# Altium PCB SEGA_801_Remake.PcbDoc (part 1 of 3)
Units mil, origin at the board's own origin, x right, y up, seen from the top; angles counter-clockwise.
Board outline 5905.51 x 7590.41 mil, 2 copper layers (Top Layer, Bottom Layer), stack 61.811 mil thick; 192 components, 203 nets, 858 pads, 614 vias.
Unrouted connection lines stored in the file: 107.
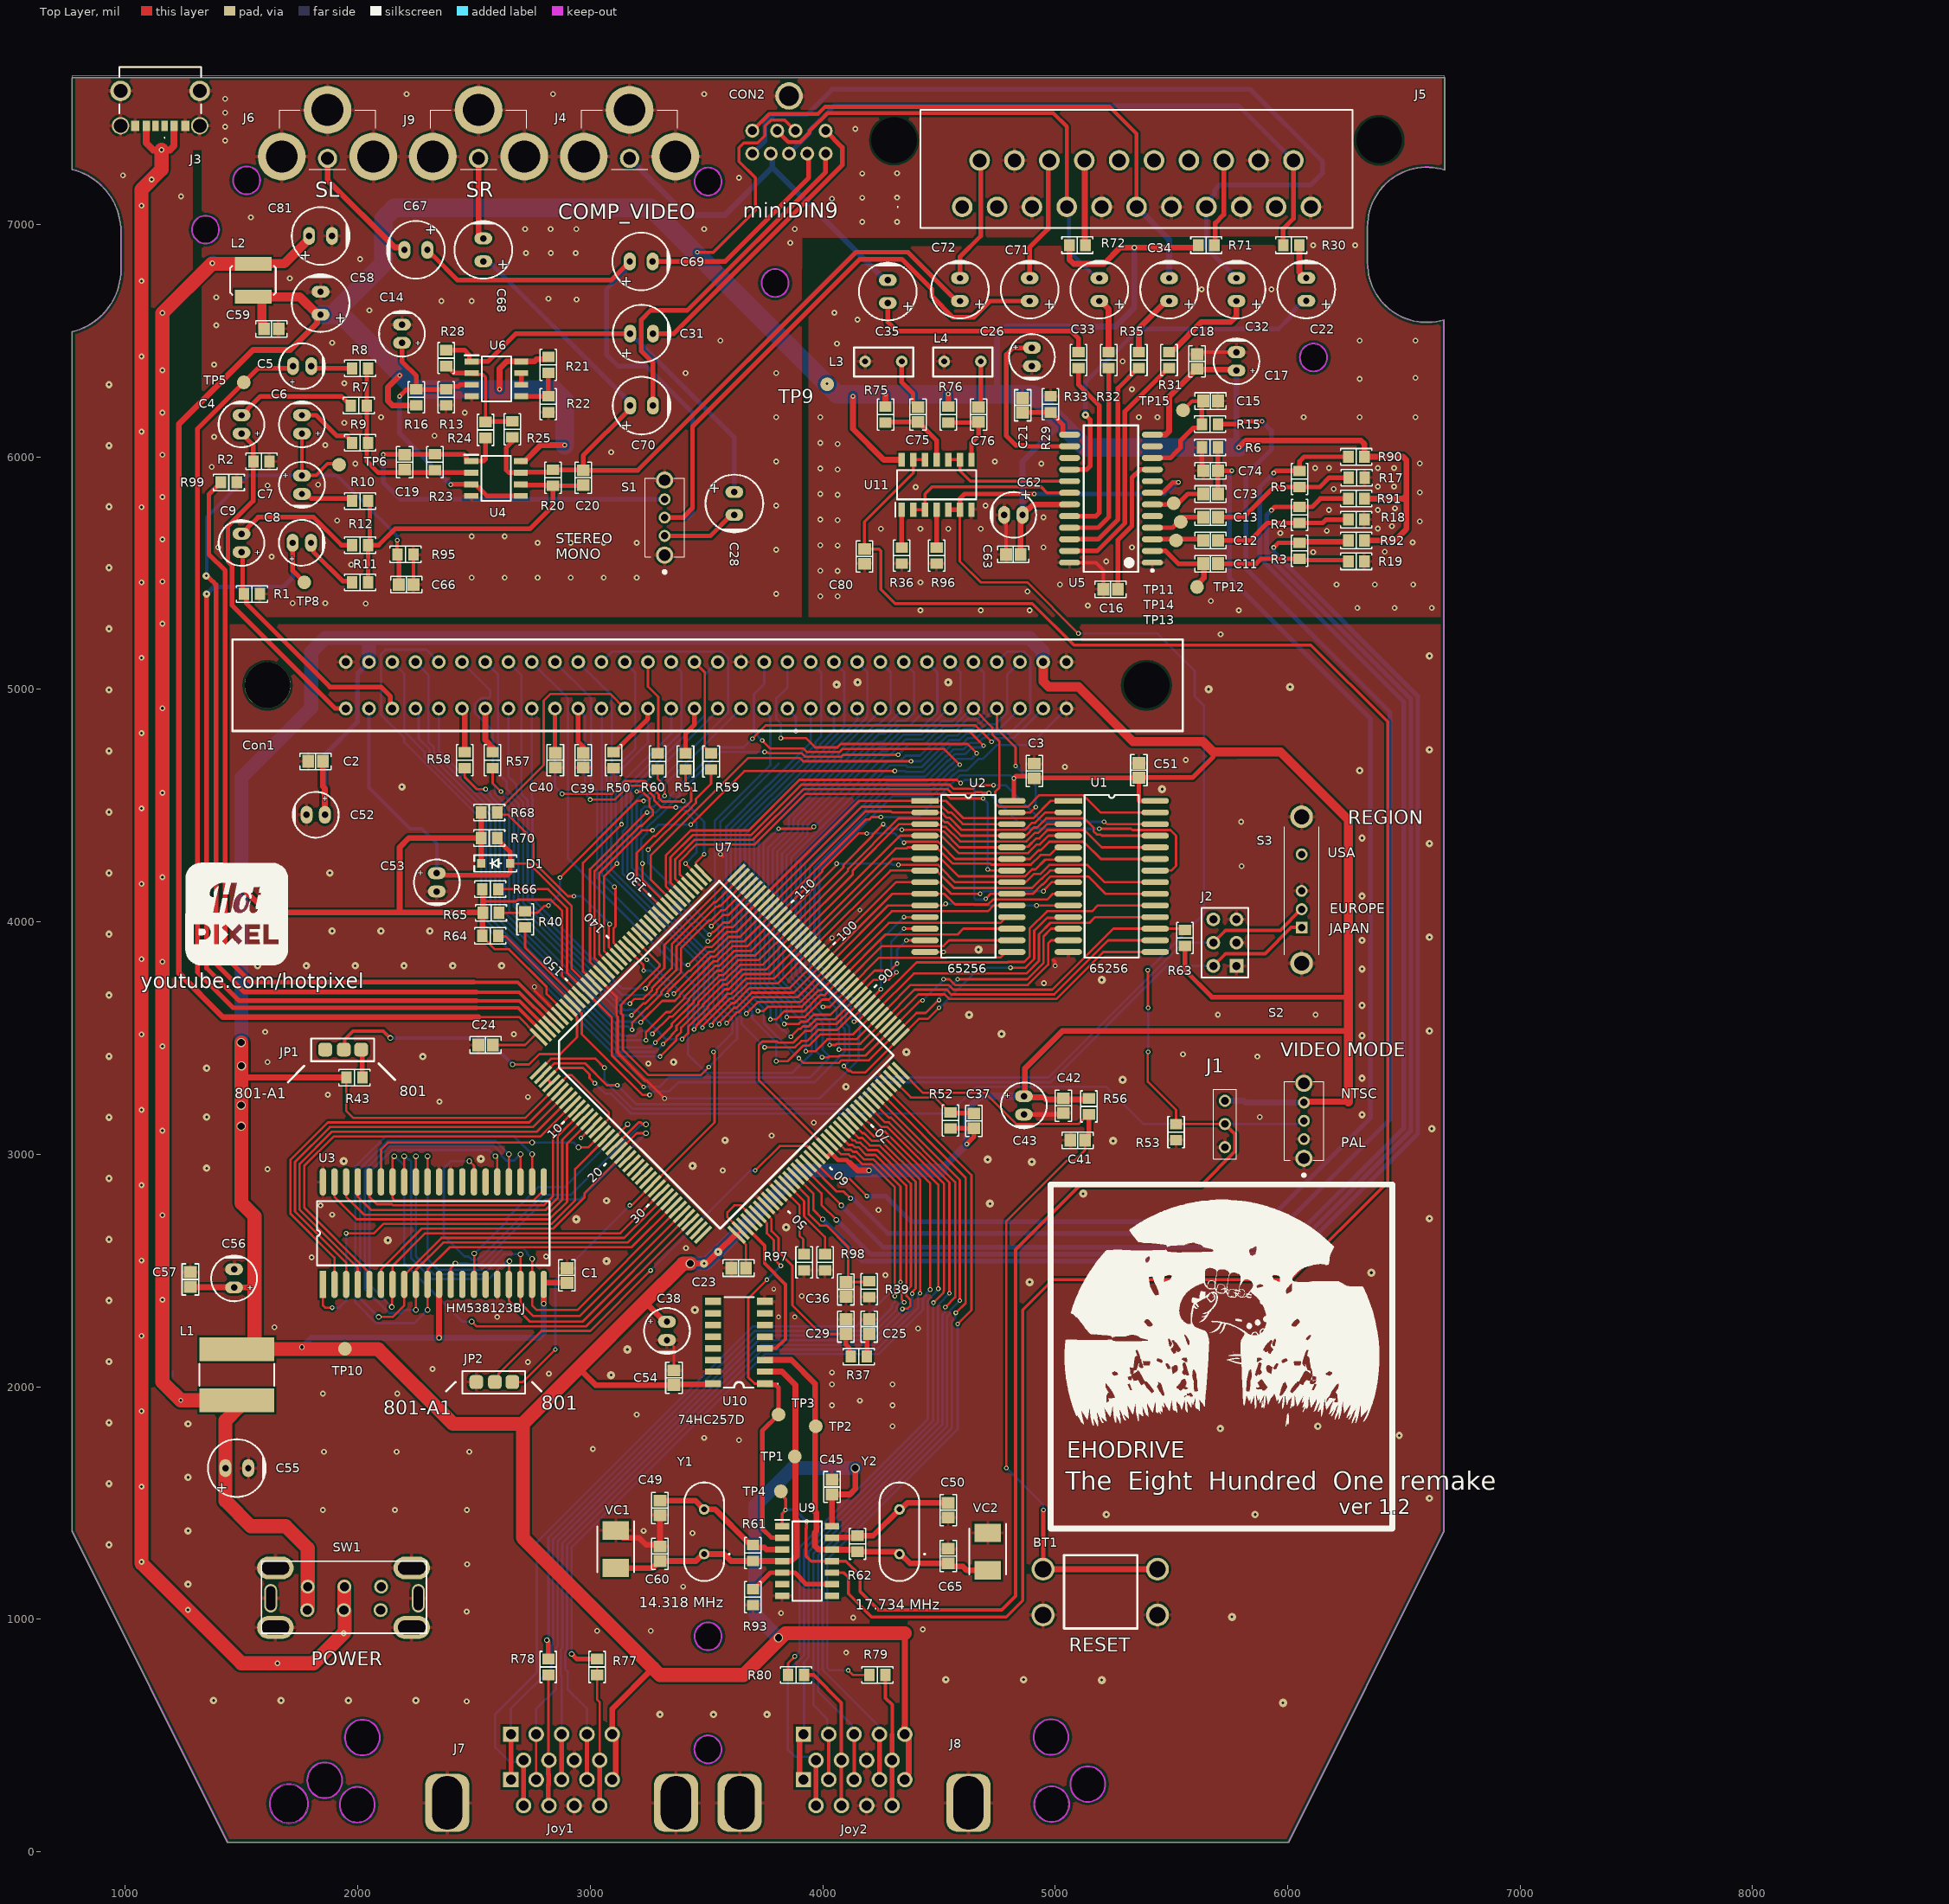
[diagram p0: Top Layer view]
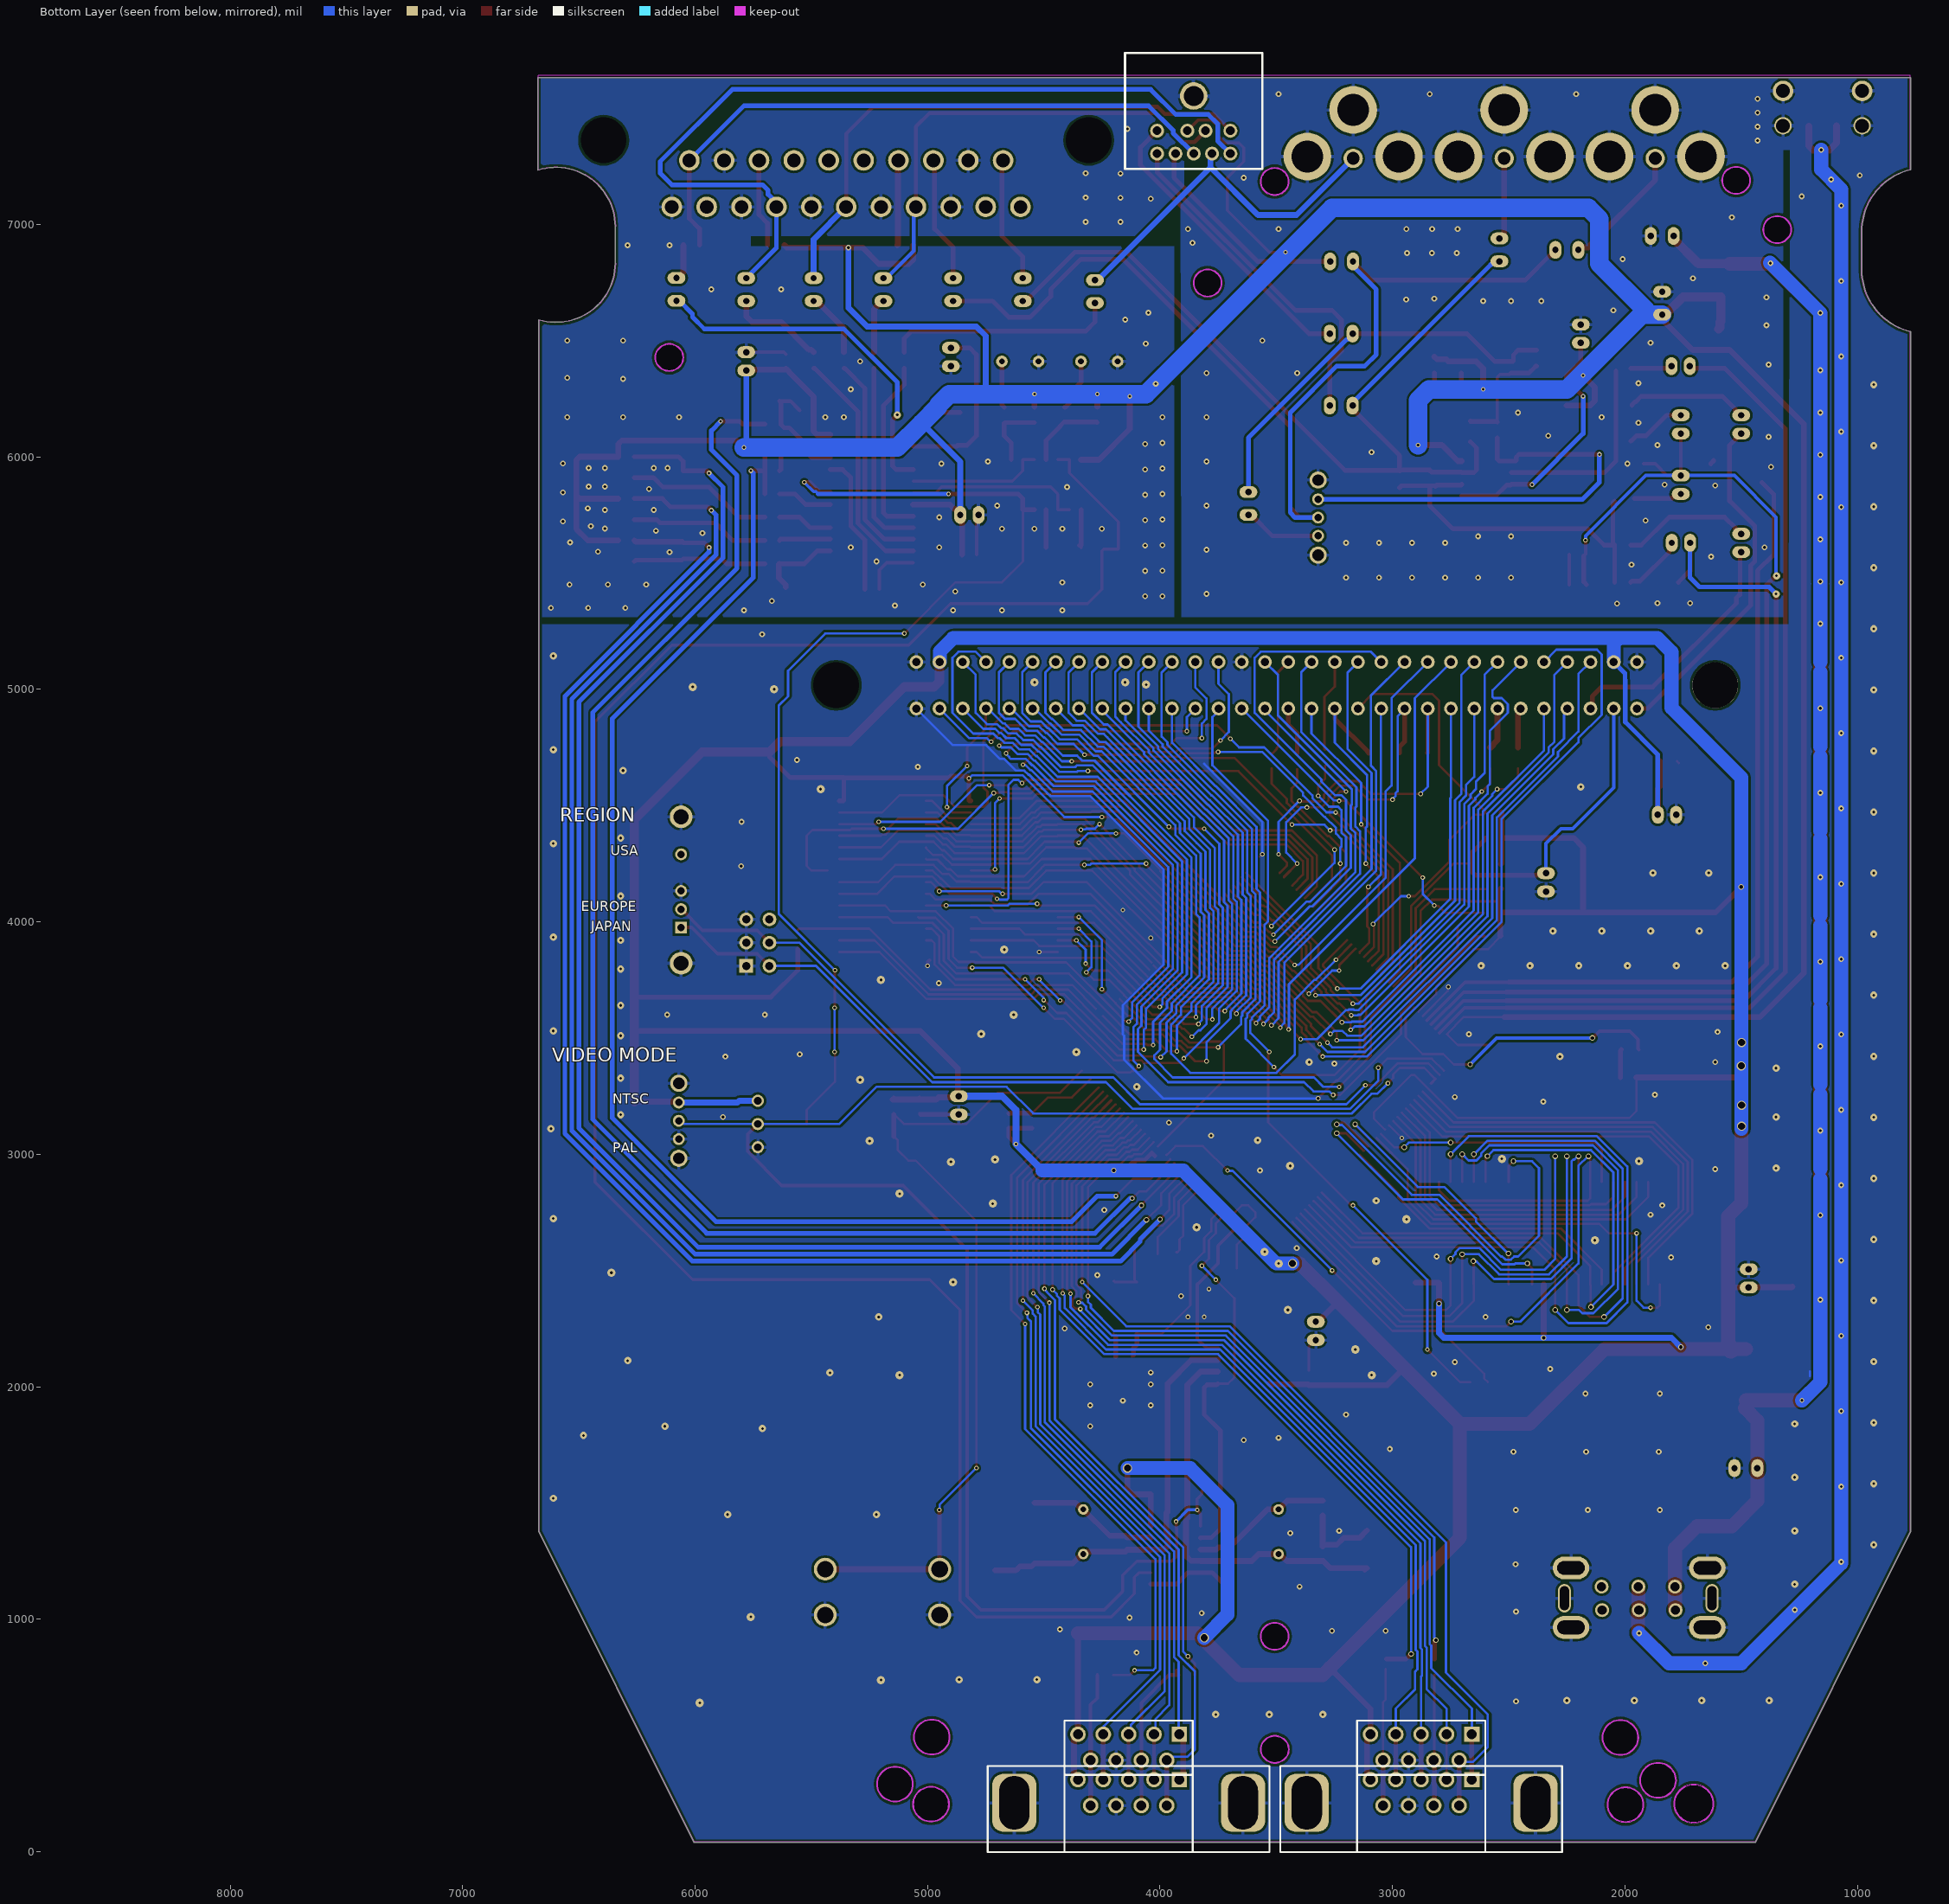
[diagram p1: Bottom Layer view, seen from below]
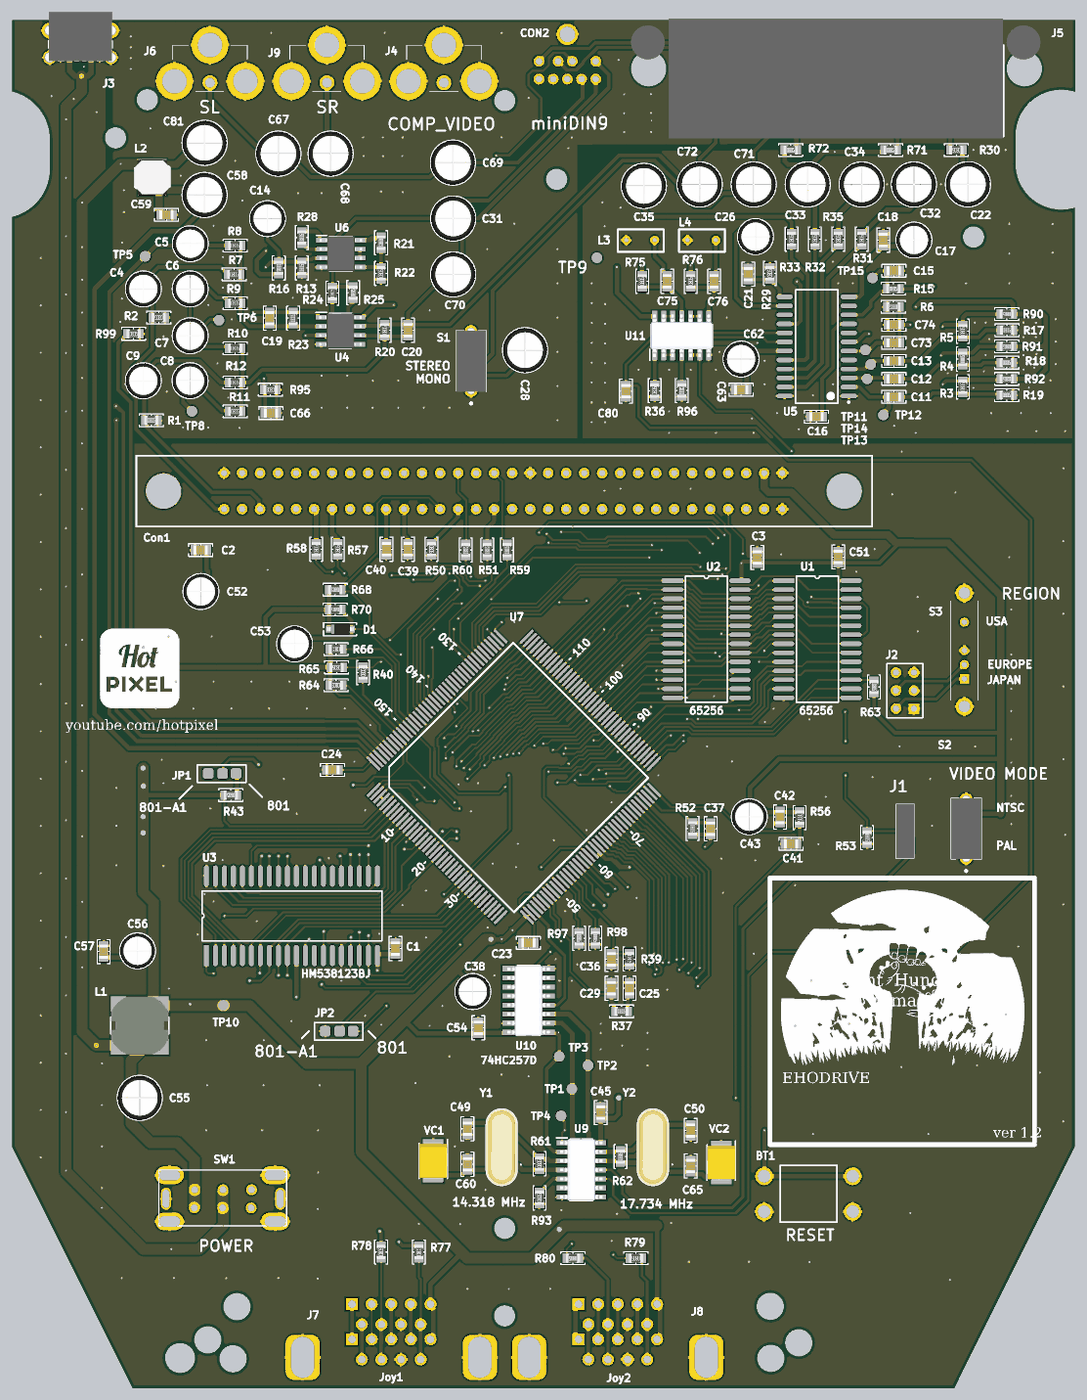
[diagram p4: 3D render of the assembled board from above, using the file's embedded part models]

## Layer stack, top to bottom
Top Solder: solder mask 0.9843, SM-004, Dk 4
Top Layer: signal copper 1.378
Dielectric 1: core 59.0551, FR4 Tg135, Dk 4.5
Bottom Layer: signal copper 1.378
Bottom Solder: solder mask 0.9843, SM-004, Dk 4

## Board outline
771,1378.35 771,6538.46 ccw(c705.6,6806.38) 981.38,6806.38 981.38,6967.36 ccw(c705.6,6967.36) 771,7235.27 771,7630 6676.51,7630 6676.51,7232.75 6676.15,7232.75 ccw(c6598.39,6990.56) 6344.02,6990.56 6344.02,6833.17 ccw(c6598.39,6833.17) 6672.57,6589.85 6672.57,1378.35 6004.03,39.59 1439.54,39.59
cut-out: 1922.01,201.93 ccw(c1997.86,201.93) 1997.86,126.08 ccw(c1997.86,201.93) 2073.71,201.93 ccw(c1997.86,201.93) 1997.86,277.78 ccw(c1997.86,201.93)
cut-out: 3736.39,6747.4 ccw(c3795.44,6747.4) 3795.44,6688.35 ccw(c3795.44,6747.4) 3854.5,6747.4 ccw(c3795.44,6747.4) 3795.44,6806.46 ccw(c3795.44,6747.4)
cut-out: 3448.14,7184.1 ccw(c3507.19,7184.1) 3507.19,7125.05 ccw(c3507.19,7184.1) 3566.25,7184.1 ccw(c3507.19,7184.1) 3507.19,7243.16 ccw(c3507.19,7184.1)
cut-out: 1463.14,7189.1 ccw(c1522.19,7189.1) 1522.19,7130.05 ccw(c1522.19,7189.1) 1581.25,7189.1 ccw(c1522.19,7189.1) 1522.19,7248.16 ccw(c1522.19,7189.1)
cut-out: 4909.15,204.15 ccw(c4985,204.15) 4985,128.3 ccw(c4985,204.15) 5060.85,204.15 ccw(c4985,204.15) 4985,280 ccw(c4985,204.15)
cut-out: 5064.35,290.61 ccw(c5140.2,290.61) 5140.2,214.75 ccw(c5140.2,290.61) 5216.05,290.61 ccw(c5140.2,290.61) 5140.2,366.46 ccw(c5140.2,290.61)
cut-out: 4906.08,492.86 ccw(c4981.93,492.86) 4981.93,417.01 ccw(c4981.93,492.86) 5057.78,492.86 ccw(c4981.93,492.86) 4981.93,568.71 ccw(c4981.93,492.86)
cut-out: 1944.07,490.97 ccw(c2019.92,490.97) 2019.92,415.12 ccw(c2019.92,490.97) 2095.77,490.97 ccw(c2019.92,490.97) 2019.92,566.82 ccw(c2019.92,490.97)
cut-out: 6051.84,6427.19 ccw(c6110.9,6427.19) 6110.9,6368.14 ccw(c6110.9,6427.19) 6169.95,6427.19 ccw(c6110.9,6427.19) 6110.9,6486.25 ccw(c6110.9,6427.19)
cut-out: 1286.39,6977.4 ccw(c1345.44,6977.4) 1345.44,6918.35 ccw(c1345.44,6977.4) 1404.5,6977.4 ccw(c1345.44,6977.4) 1345.44,7036.46 ccw(c1345.44,6977.4)
cut-out: 3448.04,925.94 ccw(c3507.09,925.94) 3507.09,866.89 ccw(c3507.09,925.94) 3566.15,925.94 ccw(c3507.09,925.94) 3507.09,985 ccw(c3507.09,925.94)
cut-out: 3447.16,439.94 ccw(c3506.22,439.94) 3506.22,380.88 ccw(c3506.22,439.94) 3565.27,439.94 ccw(c3506.22,439.94) 3506.22,498.99 ccw(c3506.22,439.94)
cut-out: 1782.01,306.93 ccw(c1857.86,306.93) 1857.86,231.08 ccw(c1857.86,306.93) 1933.71,306.93 ccw(c1857.86,306.93) 1857.86,382.78 ccw(c1857.86,306.93)
cut-out: 1620.59,206.07 cw(c1703.93,206.07) 1703.93,289.41 cw(c1703.93,206.07) 1787.27,206.07 cw(c1703.93,206.07) 1703.93,122.73 cw(c1703.93,206.07)

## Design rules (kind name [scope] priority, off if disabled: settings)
BoardOutlineClearance [All] p1 off: gap=10 ignorepadtopadclearanceinfootprint=FALSE except(0: Arc-SplitContinuation Track-SplitContinuation SMDPad-SplitContinuation THPad-SplitContinuation Via-SplitContinuation Fill-SplitContinuation Poly-SplitContinuation Region-SplitContinuation Text-SplitContinuation)
Clearance Clearance_Gen [InNetClass('GEN')] p1: gap=20 ignorepadtopadclearanceinfootprint=TRUE except(40: Track-Poly)
Clearance Clearance_ram [InNetClass('RAM bus')] p2: gap=10 ignorepadtopadclearanceinfootprint=TRUE except(5: Arc-SMDPad Track-SMDPad)
Clearance [All] p3 off: gap=10 ignorepadtopadclearanceinfootprint=FALSE except(0: Arc-Hole Track-Hole SMDPad-Hole THPad-Hole Via-Hole Fill-Hole Poly-Hole Region-Hole Text-Hole)
Clearance Clearance_analog [InNetClass('Analog')] p4: gap=20 ignorepadtopadclearanceinfootprint=TRUE
Clearance Clearance_dig [All] p5: gap=10 ignorepadtopadclearanceinfootprint=TRUE except(7: Arc-SMDPad Track-SMDPad)
Clearance Clearance_pwr [InNetClass('Power')] p6: gap=20 ignorepadtopadclearanceinfootprint=TRUE
ComponentClearance [All] p1: gap=40 collisioncheckmode=3 verticalgap=40 showdistances=FALSE
FanoutControl Fanout_SOIC [IsSOIC] p3: bgadir=Out bgaviamode=Closest fanoutstyle=Auto fanoutdirection=Alternating viagrid=1 // Fanout_SOIC (Default Rule)
HoleSize [All] p1: absolutevalues=TRUE maxlimit=500 minlimit=0.98 maxpercent=80.000 minpercent=20.000
MinimumSolderMaskSliver [All] p1 off: minsoldermaskwidth=7.87
PlaneConnect [All] p1: pad.planeconnectstyle=Relief pad.reliefexpansion=10 pad.reliefentries=4 pad.reliefconductorwidth=10 pad.reliefairgap=15 via.planeconnectstyle=Relief via.reliefexpansion=10 via.reliefentries=4 via.reliefconductorwidth=20 via.reliefairgap=20
PolygonConnect [All] p1: thpad.connectstyle=Relief thpad.reliefconductorwidth=15 thpad.reliefentries=4 thpad.polygonreliefangle="90 Angle" thpad.airgapwidth=10 smdpad.connectstyle=Relief smdpad.reliefconductorwidth=13 smdpad.reliefentries=4 smdpad.polygonreliefangle="90 Angle" smdpad.airgapwidth=10 via.connectstyle=Direct via.reliefconductorwidth=10 via.reliefentries=4 via.polygonreliefangle="90 Angle" via.airgapwidth=10
RoomDefinition Sheet1 [InComponentClass('Sheet1')] p1 off: confinementstyle=ConfineOut formatcopy=TRUE lockcomponents=FALSE outline 7390,7960 7330,7960 7330,7910 7390,7910
RoutingVias [All] p1: holewidth=15.75 width=23.62 viastyle="Through Hole" minholewidth=11.81 minwidth=19.68 maxholewidth=23.62 maxwidth=39.37
SilkToSolderMaskClearance [IsPad] p1 off: minsilkscreentomaskgap=7.87 clearancetoexposedcopper=TRUE
SolderMaskExpansion [All] p1: expansion=4 istentingtop=FALSE
UnConnectedPin [All] p1 off:
UnRoutedNet [All] p1: checkbadconnections=TRUE
Width Width_VCC [InNet('AVCC') or InNet('VCC') or InNet('NetJ3_A9')  or InNet('NetC55_1')] p1: maxlimit=80 minlimit=10 preferedwidth=25 minimp=50.000000 maximp=50.000000 favimp=50.000000
Width Width_analog [InNetClass('Analog_net')] p2: maxlimit=47.99 minlimit=10 preferedwidth=47.99 impedanceprofiledriven=TRUE impedanceprofileid={D2BDD4AC-4455-4B8A-B1BE-05F7E327D7DE} impedanceprofilevalue=75.000000 minimp=50.000000 maximp=50.000000 favimp=50.000000
Width Width_1 [All] p3: maxlimit=50 minlimit=10 preferedwidth=13 minimp=50.000000 maximp=50.000000 favimp=50.000000
Width [InNet('AVCC')] p4: maxlimit=78.74 minlimit=10 preferedwidth=19.68 minimp=50.000000 maximp=50.000000 favimp=50.000000
23 further rules are at their usual default settings.

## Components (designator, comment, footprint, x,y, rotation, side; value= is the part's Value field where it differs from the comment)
BT1 "RESET" KLS7-12 4947.87,1215 r0 top locked
C1 "0.1 uF" "CAP 0805_2012" 2900,2478.5 r90 top
C2 "0.1 uF" "CAP 0805_2012" 1818.5,4690 r180 top
C3 "0.1 uF" "CAP 0805_2012" 4910,4648.5 r90 top
C4 "10 uF" "CAP TH ALUM ELEC D5.00mm S2.00mm H7.00mm" 1500,6139.37 r270 top value=47µF
C5 "10 uF" "CAP TH ALUM ELEC D5.00mm S2.00mm H7.00mm" 1760.63,6390 r180 top value=47µF
C6 "10 uF" "CAP TH ALUM ELEC D5.00mm S2.00mm H7.00mm" 1760,6139.37 r270 top value=47µF
C7 "10 uF" "CAP TH ALUM ELEC D5.00mm S2.00mm H7.00mm" 1760,5879.37 r90 top value=47µF
C8 "10 uF" "CAP TH ALUM ELEC D5.00mm S2.00mm H7.00mm" 1759.37,5630 r180 top value=47µF
C9 "10 uF" "CAP TH ALUM ELEC D5.00mm S2.00mm H7.00mm" 1500,5629.37 r270 top value=47µF
C11 "0.1 uF" "CAP 0805_2012" 5668.5,5540 r0 top
C12 "0.1 uF" "CAP 0805_2012" 5668.5,5640 r0 top
C13 "0.1 uF" "CAP 0805_2012" 5668.5,5740 r0 top
C14 "100 uF" "CAP TH ALUM ELEC D5.00mm S2.00mm H7.00mm" 2190,6529.37 r270 top value=47µF
C15 "47 pF" "CAP 0805_2012" 5668.5,6240 r0 top
C16 "0.1 uF" "CAP 0805_2012" 5238.5,5430 r180 top
C17 "47 uF" "CAP TH ALUM ELEC D5.00mm S2.00mm H7.00mm" 5780,6410.63 r270 top value=47µF
C18 "100 pF" "CAP 0805_2012" 5610,6410 r90 top
C19 "470 pF" "CAP 0805_2012" 2201.48,5977.03 r270 top
C20 "470 pF" "CAP 0805_2012" 2970,5910 r270 top
C21 "0.1 uF" "CAP 0805_2012" 4860,6221.5 r90 top
C22 "330 uF" "CAP TH ALUM ELEC D6.30mm S2.50mm H12.50mm" 6080,6720 r270 top value=33µF
C23 "0.1 uF" "CAP 0805_2012" 3638.5,2510 r180 top
C24 "0.1 uF" "CAP 0805_2012" 2550,3470 r180 top
C25 "10 nF" "CAP 0805_2012" 4200,2258.5 r90 top
C26 "10 uF" "CAP TH ALUM ELEC D5.00mm S2.00mm H7.00mm" 4900,6429.37 r90 top value=47µF
C28 "220 uF" "CAP TH ALUM ELEC D6.30mm S2.50mm H12.50mm" 3620,5799.21 r90 top value=33µF
C29 "24 pF" "CAP 0805_2012" 4100,2258.5 r90 top
C31 "220 uF" "CAP TH ALUM ELEC D6.30mm S2.50mm H12.50mm" 3220.79,6530 r180 top value=33µF
C32 "220 uF" "CAP TH ALUM ELEC D6.30mm S2.50mm H12.50mm" 5780,6719.21 r270 top value=33µF
C33 "220 uF" "CAP TH ALUM ELEC D6.30mm S2.50mm H12.50mm" 5190,6719.21 r270 top value=33µF
C34 "220 uF" "CAP TH ALUM ELEC D6.30mm S2.50mm H12.50mm" 5490,6719.21 r270 top value=33µF
C35 "220 uF" "CAP TH ALUM ELEC D6.30mm S2.50mm H12.50mm" 4280,6710.79 r270 top value=33µF
C36 "10 pF" "CAP 0805_2012" 4100,2418.5 r270 top
C37 "100 pF" "CAP 0805_2012" 4650,3143.31 r90 top
C38 "10 uF" "CAP TH ALUM ELEC D5.00mm S2.00mm H7.00mm" 3330,2240 r90 top value=47µF
C39 "100 pF" "CAP 0805_2012" 2970,4694.45 r90 top
C40 "100 pF" "CAP 0805_2012" 2850,4694.45 r90 top
C41 "100 pF" "CAP 0805_2012" 5096.89,3060 r0 top
C42 "0.1 uF" "CAP 0805_2012" 5035.39,3208.5 r270 top
C43 "47 uF" "CAP TH ALUM ELEC D5.00mm S2.00mm H7.00mm" 4865.39,3210 r90 top value=47µF
C45 "0.1 uF" "CAP 0805_2012" 4040,1568.5 r90 top
C49 "30 pF" "CAP 0805_2012" 3300,1478.5 r90 top
C50 "30 pF" "CAP 0805_2012" 4540,1468.5 r90 top
C51 "0.1 uF" "CAP 0805_2012" 5360,4651.5 r90 top
C52 "100 uF" "CAP TH ALUM ELEC D5.00mm S2.00mm H7.00mm" 1819.37,4460 r0 top value=47µF
C53 "10 uF" "CAP TH ALUM ELEC D5.00mm S2.00mm H7.00mm" 2340,4169.37 r90 top value=47µF
C54 "0.1 uF" "CAP 0805_2012" 3360,2038.5 r90 top
C55 "1000 uF" "CAP TH ALUM ELEC D6.30mm S2.50mm H12.50mm" 1480,1650 r180 top value=33µF
C56 "10 uF" "CAP TH ALUM ELEC D5.00mm S2.00mm H7.00mm" 1467.91,2465.93 r270 top value=47µF
C57 "0.1 uF" "CAP 0805_2012" 1280,2461.5 r90 top
C58 "47 uF" "CAP TH ALUM ELEC D6.30mm S2.50mm H12.50mm" 1840,6660.79 r270 top value=33µF
C59 "0.1 uF" "CAP 0805_2012" 1628.5,6550 r0 top
C60 "15 pF" "CAP 0805_2012" 3300,1281.5 r90 top
C62 "47 uF" "CAP TH ALUM ELEC D5.00mm S2.00mm H7.00mm" 4820,5750 r0 top value=47µF
C63 "100 pF" "CAP 0805_2012" 4820,5580 r180 top
C65 "15 pF" "CAP 0805_2012" 4540,1271.5 r90 top
C66 "2200 pF" "CAP 0805_2012" 2208.5,5450 r0 top
C67 "220 uF" "CAP TH ALUM ELEC D6.30mm S2.50mm H12.50mm" 2250,6890 r0 top value=33µF
C68 "220 uF" "CAP TH ALUM ELEC D6.30mm S2.50mm H12.50mm" 2540,6890 r270 top value=33µF
C69 "220 uF" "CAP TH ALUM ELEC D6.30mm S2.50mm H12.50mm" 3219.21,6840 r180 top value=33µF
C70 "220 uF" "CAP TH ALUM ELEC D6.30mm S2.50mm H12.50mm" 3220.79,6220 r180 top value=33µF
C71 "220 uF" "CAP TH ALUM ELEC D6.30mm S2.50mm H12.50mm" 4890,6719.21 r270 top value=33µF
C72 "220 uF" "CAP TH ALUM ELEC D6.30mm S2.50mm H12.50mm" 4590,6719.21 r270 top value=33µF
C73 "10 pF" "CAP 0805_2012" 5668.5,5840 r180 top
C74 "100 pF" "CAP 0805_2012" 5668.5,5940 r180 top
C75 "30 pF" "CAP 0805_2012" 4410,6181.5 r90 top
C76 "39 pF" "CAP 0805_2012" 4670,6181.5 r90 top
C80 "0.1 uF" "CAP 0805_2012" 4180,5571.5 r90 top
C81 "100 uF" "CAP TH ALUM ELEC D6.30mm S2.50mm H12.50mm" 1840,6950 r180 top value=33µF
Con1 "Cartridge slot" CARD_SLOT 1462.17,5218.47 r0 top locked
CON2 "miniDIN9" MINIDIN9 3855,7303.82 r0 top locked
D1 "1N4148W" SOD-123 2593.62,4250.63 r180 top
J1 "SW MODE HEADER" 8018700310012101 5730,3030 r90 top
J2 "REGION HEADER" HDR2X3 5780,3810 r90 top locked
J3 "USB TYPE-C" UJCHP3SMTTR 1150,7540 r180 top locked
J4 "COMP_VIDEO" 1610390E 3169.29,7283.46 r180 top locked
J5 "SCART" PSG01601 4600,7074.8 r180 top locked
J6 "SL" 1610390E 1870.08,7283.46 r180 top locked
J7 "D Connector 9 Long" DSUB1.385-2H9_LONG 2876.89,75 r180 top
J8 "D Connector 9 Long" DSUB1.385-2H9_LONG 4135,75 r180 top
J9 "SR" 1610390E 2519.68,7283.46 r180 top locked
Joy1 "D Connector 9" DSUB1.385-2H9#1 2876.89,-120 r180 top
Joy2 "D Connector 9" DSUB1.385-2H9#2 4135,-120 r180 top
JP1 "SM801" JUMPERPAD 2015,3450 r270 top
JP2 "SM801/A" JUMPERPAD 2665,2020 r270 top
L1 "10 uH" "BOURNS SRN8040" 1480,2051.42 r90 top value="1.5 µH"
L2 "10uH" "TAIYO YUDEN NRS5030" 1550,6759.13 r270 top value="33 µH"
L3 "Inductor" "INDUCTOR VERTICAL" 4340,6410 r180 top
L4 "Inductor" "INDUCTOR VERTICAL" 4680,6410 r180 top
R1 "75" "RES 0805_2012" 1544.45,5410 r0 top
R2 "75" "RES 0805_2012" 1585.55,5980 r180 top
R3 "7.5k" "RES 0805_2012" 6051.1,5595.55 r90 top
R4 "7.5k" "RES 0805_2012" 6051.1,5750 r90 top
R5 "7.5k" "RES 0805_2012" 6051.1,5904.45 r90 top
R6 "1k" "RES 0805_2012" 5665.55,6040 r180 top
R7 "47k" "RES 0805_2012" 2004.45,6220 r0 top
R8 "20k" "RES 0805_2012" 2010,6380 r0 top
R9 "47k" "RES 0805_2012" 2010,6060 r0 top
R10 "47k" "RES 0805_2012" 2010,5810 r0 top
R11 "20k" "RES 0805_2012" 2010,5460 r0 top
R12 "47k" "RES 0805_2012" 2010,5620 r0 top
R13 "1k" "RES 0805_2012" 2380,6255.55 r90 top
R15 "10k" "RES 0805_2012" 5665.55,6140 r0 top
R16 "1.5k" "RES 0805_2012" 2252.08,6255.55 r270 top
R17 "1.8k" "RES 0805_2012" 6296.66,5910 r0 top
R18 "1.8k" "RES 0805_2012" 6295.55,5730 r0 top
R19 "1.8k" "RES 0805_2012" 6295.55,5550 r0 top
R20 "47k" "RES 0805_2012" 2840,5910 r90 top
R21 "10k" "RES 0805_2012" 2820,6395.55 r270 top
R22 "10k" "RES 0805_2012" 2820,6225.55 r90 top
R23 "47k" "RES 0805_2012" 2331.48,5977.03 r90 top
R24 "22k" "RES 0805_2012" 2550,6115.55 r90 top
R25 "22k" "RES 0805_2012" 2665.04,6118.58 r90 top
R28 "22k" "RES 0805_2012" 2380,6424.45 r90 top value=12k
R29 "47k" "RES 0805_2012" 4980,6225.55 r90 top
R30 "75" "RES 0805_2012" 6015.55,6910 r180 top
R31 "75" "RES 0805_2012" 5490,6415.55 r90 top
R32 "75" "RES 0805_2012" 5230,6415.55 r90 top
R33 "75" "RES 0805_2012" 5100,6415.55 r90 top
R35 "75" "RES 0805_2012" 5360,6415.55 r90 top
R36 "15k" "RES 0805_2012" 4340,5574.45 r90 top
R37 "10k" "RES 0805_2012" 4155.55,2130 r0 top
R39 "1k" "RES 0805_2012" 4200,2420 r270 top
R40 "150" "RES 0805_2012" 2720,4010 r90 top
R43 "330" "RES 0805_2012" 1985.55,3330 r180 top
R50 "1.2k" "RES 0805_2012" 3100,4694.45 r270 top
R51 "100" "RES 0805_2012" 3410,4690 r90 top
R52 "2.2k" "RES 0805_2012" 4550,3144.8 r270 top
R53 "1.2k" "RES 0805_2012" 5520,3094.45 r270 top
R56 "2.2k" "RES 0805_2012" 5145.39,3205.55 r270 top
R57 "56" "RES 0805_2012" 2580,4694.45 r90 top
R58 "56" "RES 0805_2012" 2460,4694.45 r90 top
R59 "56" "RES 0805_2012" 3520,4690 r90 top
R60 "56" "RES 0805_2012" 3290,4690 r90 top
R61 "1M" "RES 0805_2012" 3700,1284.45 r90 top
R62 "1M" "RES 0805_2012" 4150,1324.45 r90 top
R63 "3.3k" "RES 0805_2012" 5558.13,3929.91 r270 top
R64 "2.2k" "RES 0805_2012" 2570,3940 r180 top
R65 "2.2k" "RES 0805_2012" 2573.07,4038.5 r180 top
R66 "3.3k" "RES 0805_2012" 2570,4140 r180 top
R68 "1.2k" "RES 0805_2012" 2565.55,4470 r180 top
R70 "47k" "RES 0805_2012" 2565.55,4360 r180 top
R71 "180" "RES 0805_2012" 5650,6910 r0 top
R72 "180" "RES 0805_2012" 5095.55,6910 r0 top
R75 "2.6k" "RES 0805_2012" 4270,6181.5 r90 top
R76 "3.3k" "RES 0805_2012" 4540,6181.5 r90 top
R77 "330" "RES 0805_2012" 3030,794.45 r90 top
R78 "330" "RES 0805_2012" 2820,794.45 r90 top
R79 "330" "RES 0805_2012" 4235.55,760 r180 top
R80 "330" "RES 0805_2012" 3885.55,760 r180 top
R90 "5.6k" "RES 0805_2012" 6295.55,6000 r180 top
R91 "5.6k" "RES 0805_2012" 6295.55,5820 r180 top
R92 "5.6k" "RES 0805_2012" 6295.55,5640 r180 top
R93 "4.7k" "RES 0805_2012" 3700,1094.45 r90 top
R95 "2.2k" "RES 0805_2012" 2205.55,5580 r180 top
R96 "15k" "RES 0805_2012" 4490,5575.55 r90 top
R97 "1k" "RES 0805_2012" 3920,2535.55 r270 top
R98 "1k" "RES 0805_2012" 4010,2535.55 r270 top
R99 "000" "RES 0805_2012" 1445.55,5890 r0 top
S1 "SW_MONO" SS12D07VG4NSGAPA 3320,5659.84 r90 top
S2 "SW_MODE" SS12D07VG4NSGAPA 6070,3065.04 r90 top
S3 "REGION-SW" SK13D08G5E 6060,3975.04 r90 top
SW1 "POWER SW" SW_6_4 1940.63,1040 r0 top locked
TP1 "Test point" TP 3880,1700 r0 top
TP2 "Test point" TP 3970,1830 r0 top
TP3 "Test point" TP 3810,1880 r0 top
TP4 "Test point" TP 3820,1550 r0 top
TP5 "Test point" TP 1510,6320 r0 top
TP6 "Test point" TP 1919.93,5965.47 r0 top
TP8 "Test point" TP 1770,5460 r0 top
TP9 "Test point" TP 4019.13,6312.04 r90 top
TP10 "Test point" TP 1944.82,2163.16 r90 top
TP11 "Test point" TP 5510,5800 r90 top
TP12 "Test point" TP 5610,5440 r90 top
TP13 "Test point" TP 5520,5640 r90 top
TP14 "Test point" TP 5540,5720 r90 top
TP15 "Test point" TP 5550,6200 r90 top
U1 "65256" SOP28 5056.38,4520 r0 top
U2 "65256" SOP28 4440,4520 r0 top locked
U3 "HM538123BJ" SOP40 1825,2515 r90 top locked
U4 "4558" SOIC127P600X175-8N 2595.04,5906.72 r0 top
U5 "CXA1645M (CXA2075M)" SOP24N 5240,5820 r180 top
U6 "4558" SOIC127P600X175-8N 2596.77,6335 r0 top
U7 "SM801" SM801-A1 2777.16,3433.03 r45 top locked
U9 "74hc04" SOIC127P600X175-14N 3932.72,1250 r0 top
U10 "74HC257D" 74HC257D652 3640,2190 r90 top
U11 "HEF4066BT" SOIC127P600X175-14N 4490,5880 r90 top
VC1 "4-10 pF" CAPPM5040X320N 3110,1300.71 r270 top
VC2 "4-10 pF" CAPPM5040X320N 4710,1290.71 r270 top
Y1 "14.318 MHz" 12000MHzHC494H3050408518pFATF 3490,1280 r90 top
Y2 "17.734 MHz" 12000MHzHC494H3050408518pFATF 4330,1280 r90 top

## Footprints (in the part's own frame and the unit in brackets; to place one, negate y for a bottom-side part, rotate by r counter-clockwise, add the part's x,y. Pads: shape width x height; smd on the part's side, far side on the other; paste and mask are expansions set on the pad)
74HC257D652 [mm]
  rect 0.8x1.75 smd: 1(-4.495,-2.825) 8(4.495,-2.825) 9(4.495,2.825) 16(-4.495,2.825)
  rect 0.7x1.75 smd: 2(-3.175,-2.825) 3(-1.905,-2.825) 4(-0.635,-2.825) 5(0.635,-2.825) 6(1.905,-2.825) 7(3.175,-2.825) 10(3.175,2.825) 11(1.905,2.825) 12(0.635,2.825) 13(-0.635,2.825) 14(-1.905,2.825) 15(-3.175,2.825)
  silkscreen extent -4.92,-4.3 4.95,1.67, body extent -4.95,-3 4.95,3, height 1.56
12000MHzHC494H3050408518pFATF [mm]
  round 1.155 hole 0.63: 1(0,0) 2(4.88,0)
  silkscreen extent -2.94,-2.8 7.82,2.17, body extent -2.95,-2.17 7.83,2.17, height 3.5
1610390E [mm]
  round 2.1 hole 1.4: 1(0,0)
  round 5.218 hole 3.478: 2(-5,-0.2) 3(0,-5.3) 4(5,-0.2)
  silkscreen extent -5.25,-5.3 5.25,1.2
8018700310012101 [mm]
  round 1.333 hole 0.82: 1(0,0) 2(2.54,0) 3(5.08,0)
  silkscreen extent -1.27,-1.27 6.35,1.27, body extent -1.27,-1.27 6.35,1.27, height 4.3
"BOURNS SRN8040" [mm] "Power Inductor, 2-Leads, Bourns, SRN8040-220M"
  rect 2.6x8.2 smd: 1(-2.8,0) 2(2.8,0)
  silkscreen extent -1.2,-4.07 1.2,4.08, body extent -4.08,-4.07 4.07,4.08, height 4
"CAP 0805_2012" [mm] "Chip Capacitor, 2-Leads, Body 2.00x1.20mm, IPC Medium Density"
  rect 1.3x1.4 smd: 1(-0.8,0) 2(0.8,0)
  silkscreen extent -1.7,-0.9 1.7,0.9, body extent -1,-0.64 1,0.64, height 1.26
"CAP TH ALUM ELEC D5.00mm S2.00mm H7.00mm" [mm] "5mm Diameter 2mm Lead Spacing Aluminum Electrolytic Capacitors Radial, Can"
  oval 1.3x1.95 hole 0.7: 1(1,0) 2(-1,0)
  silkscreen extent -2.5,-2.5 2.5,2.5, body extent -2.51,-2.5 2.5,2.5, height 7
"CAP TH ALUM ELEC D6.30mm S2.50mm H12.50mm" [mm] "6.3mm Diameter 2.5mm Lead Spacing Aluminum Electrolytic Capacitors Radial, Can"
  oval 1.3x1.95 hole 0.7: 1(1.25,0) 2(-1.25,0)
  silkscreen extent -3.15,-3.15 3.15,3.15, body extent -3.16,-3.15 3.15,3.15, height 12.5
CAPPM5040X320N [mm]
  rect 2x2.9 smd: 1(-2.05,0) 2(2.05,0)
  silkscreen extent -3.05,-2 2.5,2, body extent -2.5,-2 2.5,2, height 3.2
CARD_SLOT [mm]
  round 1.5 hole 0.9: 1(12.351,-7.652) 2(14.891,-7.652) 3(17.431,-7.652) 4(19.971,-7.652) 5(22.511,-7.652) 6(25.051,-7.652) 7(27.591,-7.652) 8(30.131,-7.652) 9(32.671,-7.652) 10(35.211,-7.652) 11(37.751,-7.652) 12(40.291,-7.652) 13(42.831,-7.652) 14(45.371,-7.652) 15(47.911,-7.652) 16(50.451,-7.652) 17(52.991,-7.652) 18(55.531,-7.652) 19(58.071,-7.652) 20(60.611,-7.652) 21(63.151,-7.652) 22(65.691,-7.652) 23(68.231,-7.652) 24(70.771,-7.652) 25(73.311,-7.652) 26(75.851,-7.652) 27(78.391,-7.652) 28(80.931,-7.652) 29(83.471,-7.652) 30(86.011,-7.652) 31(88.551,-7.652) 32(91.091,-7.652) 33(91.091,-2.572) 34(88.551,-2.572) 35(86.011,-2.572) 36(83.471,-2.572) 37(80.931,-2.572) 38(78.391,-2.572) 39(75.851,-2.572) 40(73.311,-2.572) 41(70.771,-2.572) 42(68.231,-2.572) 43(65.691,-2.572) 44(63.151,-2.572) 45(60.611,-2.572) 46(58.071,-2.572) 47(55.531,-2.572) 48(52.991,-2.572) 49(50.451,-2.572) 50(47.911,-2.572) 51(45.371,-2.572) 52(42.831,-2.572) 53(40.291,-2.572) 54(37.751,-2.572) 55(35.211,-2.572) 56(32.671,-2.572) 57(30.131,-2.572) 58(27.591,-2.572) 59(25.051,-2.572) 60(22.511,-2.572) 61(19.971,-2.572) 62(17.431,-2.572) 63(14.891,-2.572) 64(12.351,-2.572)
  round 5 hole 5: 65(3.805,-5.112)
  round 4 hole 5: 66(99.835,-5.112)
  silkscreen extent -0.03,-10.11 103.79,-0.11
DSUB1.385-2H9#1 [mm] "Connector; D Subminiature; 9 Position; Right Angle; Pitch 1.385 mm"
  rect 1.69x1.69 hole 1.09: 1(5.54,-10.92)
  round 1.69 hole 1.09: 2(2.77,-10.92) 3(0,-10.92) 4(-2.77,-10.92) 5(-5.54,-10.92) 6(4.155,-8.08) 7(1.385,-8.08) 8(-1.385,-8.08) 9(-4.155,-8.08)
  rrect50% 4.826x6.35 hole 3.302 slot 5.842 at 90 deg: 10(12.495,-8.382) 11(-12.495,-8.382)
DSUB1.385-2H9#2 [mm] "Connector; D Subminiature; 9 Position; Right Angle; Pitch 1.385 mm"
  rect 1.69x1.69 hole 1.09: 1(5.54,-10.92)
  round 1.69 hole 1.09: 2(2.77,-10.92) 3(0,-10.92) 4(-2.77,-10.92) 5(-5.54,-10.92) 6(4.155,-8.08) 7(1.385,-8.08) 8(-1.385,-8.08) 9(-4.155,-8.08)
  rrect50% 4.826x6.35 hole 3.26 slot 5.842 at 90 deg: 10(12.495,-8.382)
  rrect50% 4.826x6.35 hole 3.302 slot 5.842 at 90 deg: 11(-12.495,-8.382)
DSUB1.385-2H9_LONG [mm] "Connector; D Subminiature; 9 Position; Right Angle; Pitch 1.385 mm"
  rect 1.69x1.69 hole 1.09: 1(5.54,-10.92)
  round 1.69 hole 1.09: 2(2.77,-10.92) 3(0,-10.92) 4(-2.77,-10.92) 5(-5.54,-10.92) 6(4.155,-8.08) 7(1.385,-8.08) 8(-1.385,-8.08) 9(-4.155,-8.08)
HDR2X3 [mm] "Connector; Header; 3x2 Position"
  rect 1.5x1.5 hole 0.9: 1(0,0)
  round 1.5 hole 0.9: 2(0,2.54) 3(2.54,0) 4(2.54,2.54) 5(5.08,0) 6(5.08,2.54)
  silkscreen extent -1.27,-1.27 6.35,3.81
"INDUCTOR VERTICAL" [mm]
  round 1.27 hole 0.635: 1(0,0) 2(4,0)
  silkscreen extent -1.27,-1.52 5.21,1.65
JUMPERPAD [mm]
  rrect50% 1.5x1.5 smd: 1(0,0) 2(0,-1.905) 3(0,-3.937)
  silkscreen extent -1.21,-5.46 1.27,1.4
KLS7-12 [mm]
  round 2.5 hole 1.8: 1(0,0) 2(12.5,0) 3(0,-5) 4(12.5,-5)
  silkscreen extent 2.29,-6.48 10.29,1.52
MINIDIN9 [mm]
  round 1.524 hole 0.95: 1(-1.3,2.5) 2(0.7,2.5) 3(-4,2.5) 4(-2,0) 5(0,0) 6(4,2.5) 7(-4,0) 8(2,0) 9(4,0)
  round 3 hole 2.2: 10(0,6.3)
PSG01601 [mm]
  round 2.25 hole 1.5: 1(0,0) 2(-1.905,-5.08) 3(-3.81,0) 4(-5.715,-5.08) 5(-7.62,0) 6(-9.525,-5.08) 7(-11.43,0) 8(-13.335,-5.08) 9(-15.24,0) 10(-17.145,-5.08) 11(-19.05,0) 12(-20.955,-5.08) 13(-22.86,0) 14(-24.765,-5.08) 15(-26.67,0) 16(-28.575,-5.08) 17(-30.48,0) 18(-32.385,-5.08) 19(-34.29,0) 20(-36.195,-5.08) 21(-38.1,0)
  round 2.5 hole 5 unplated: MH1(-45.55,-7.28) MH2(7.45,-7.28)
  silkscreen extent -42.65,-10.6 7.1,2.29, body extent -47.81,-14.31 9.97,2.54, height 16.8
"RES 0805_2012" [mm] "Chip Resistor, 2-Leads, Body 2.00x1.25mm, IPC Medium Density"
  rect 1.15x1.35 smd: 1(-0.875,0) 2(0.875,0)
  silkscreen extent -1.7,-0.9 1.7,0.9, body extent -1,-0.62 1,0.63, height 0.6
SK13D08G5E [mm]
  rect 1.3x1.3 hole 0.8: 1(0,0)
  round 1.3 hole 0.8: 2(2,0) 3(4,0) 4(8,0)
  round 2.475 hole 1.65: MH1(-3.9,0) MH2(12.1,0)
  silkscreen extent -3,-1.9 11,1.9
SM801-A1 [mil]
  rect 100x15 smd: 1(-50.75,-53.45) 2(-50.75,-79.05) 3(-50.75,-104.65) 4(-50.75,-130.25) 5(-50.75,-155.85) 6(-50.75,-181.45) 7(-50.75,-207.05) 8(-50.75,-232.65) 9(-50.75,-258.25) 10(-50.75,-283.85) 11(-50.75,-309.45) 12(-50.75,-335.05) 13(-50.75,-360.65) 14(-50.75,-386.25) 15(-50.75,-411.85) 16(-50.75,-437.45) 17(-50.75,-463.05) 18(-50.75,-488.65) 19(-50.75,-514.25) 20(-50.75,-539.85) 21(-50.75,-565.45) 22(-50.75,-591.05) 23(-50.75,-616.65) 24(-50.75,-642.25) 25(-50.75,-667.85) 26(-50.75,-693.45) 27(-50.75,-719.05) 28(-50.75,-744.65) 29(-50.75,-770.25) 30(-50.75,-795.85) 31(-50.75,-821.45) 32(-50.75,-847.05) 33(-50.75,-872.65) 34(-50.75,-898.25) 35(-50.75,-923.85) 36(-50.75,-949.45) 37(-50.75,-975.05) 38(-50.75,-1000.65) 39(-50.75,-1026.25) 40(-50.75,-1051.85) 81(1152.45,-1051.85) 82(1152.45,-1026.25) 83(1152.45,-1000.65) 84(1152.45,-975.05) 85(1152.45,-949.45) 86(1152.45,-923.85) 87(1152.45,-898.25) 88(1152.45,-872.65) 89(1152.45,-847.05) 90(1152.45,-821.45) 91(1152.45,-795.85) 92(1152.45,-770.25) 93(1152.45,-744.65) 94(1152.45,-719.05) 95(1152.45,-693.45) 96(1152.45,-667.85) 97(1152.45,-642.25) 98(1152.45,-616.65) 99(1152.45,-591.05) 100(1152.45,-565.45) 101(1152.45,-539.85) 102(1152.45,-514.25) 103(1152.45,-488.65) 104(1152.45,-463.05) 105(1152.45,-437.45) 106(1152.45,-411.85) 107(1152.45,-386.25) 108(1152.45,-360.65) 109(1152.45,-335.05) 110(1152.45,-309.45) 111(1152.45,-283.85) 112(1152.45,-258.25) 113(1152.45,-232.65) 114(1152.45,-207.05) 115(1152.45,-181.45) 116(1152.45,-155.85) 117(1152.45,-130.25) 118(1152.45,-104.65) 119(1152.45,-79.05) 120(1152.45,-53.45)
  rect 15x100 smd: 41(51.65,-1154.25) 42(77.25,-1154.25) 43(102.85,-1154.25) 44(128.45,-1154.25) 45(154.05,-1154.25) 46(179.65,-1154.25) 47(205.25,-1154.25) 48(230.85,-1154.25) 49(256.45,-1154.25) 50(282.05,-1154.25) 51(307.65,-1154.25) 52(333.25,-1154.25) 53(358.85,-1154.25) 54(384.45,-1154.25) 55(410.05,-1154.25) 56(435.65,-1154.25) 57(461.25,-1154.25) 58(486.85,-1154.25) 59(512.45,-1154.25) 60(538.05,-1154.25) 61(563.65,-1154.25) 62(589.25,-1154.25) 63(614.85,-1154.25) 64(640.45,-1154.25) 65(666.05,-1154.25) 66(691.65,-1154.25) 67(717.25,-1154.25) 68(742.85,-1154.25) 69(768.45,-1154.25) 70(794.05,-1154.25) 71(819.65,-1154.25) 72(845.25,-1154.25) 73(870.85,-1154.25) 74(896.45,-1154.25) 75(922.05,-1154.25) 76(947.65,-1154.25) 77(973.25,-1154.25) 78(998.85,-1154.25) 79(1024.45,-1154.25) 80(1050.05,-1154.25) 121(1050.05,48.95) 122(1024.45,48.95) 123(998.85,48.95) 124(973.25,48.95) 125(947.65,48.95) 126(922.05,48.95) 127(896.45,48.95) 128(870.85,48.95) 129(845.25,48.95) 130(819.65,48.95) 131(794.05,48.95) 132(768.45,48.95) 133(742.85,48.95) 134(717.25,48.95) 135(691.65,48.95) 136(666.05,48.95) 137(640.45,48.95) 138(614.85,48.95) 139(589.25,48.95) 140(563.65,48.95) 141(538.05,48.95) 142(512.45,48.95) 143(486.85,48.95) 144(461.25,48.95) 145(435.65,48.95) 146(410.05,48.95) 147(384.45,48.95) 148(358.85,48.95) 149(333.25,48.95) 150(307.65,48.95) 151(282.05,48.95) 152(256.45,48.95) 153(230.85,48.95) 154(205.25,48.95) 155(179.65,48.95) 156(154.05,48.95) 157(128.45,48.95) 158(102.85,48.95) 159(77.25,48.95) 160(51.65,48.95)
  silkscreen extent -140,-1250 1240,150
SOD-123 [mm] "SOD, 2-Leads, Body 1.55x3.70mm, IPC Medium Density"
  rect 0.9x0.95 smd: 1(-1.575,0) 2(1.575,0)
  silkscreen extent -2.3,-0.92 2.41,0.92, body extent -1.86,-0.78 1.86,0.77, height 1.35
SOIC127P600X175-8N [mm]
  rect 1.525x0.65 smd: 1(-2.712,1.905) 2(-2.712,0.635) 3(-2.712,-0.635) 4(-2.712,-1.905) 5(2.712,-1.905) 6(2.712,-0.635) 7(2.712,0.635) 8(2.712,1.905)
  silkscreen extent -3.47,-2.45 1.6,2.58, body extent -3,-2.45 3,2.45, height 1.75
SOIC127P600X175-14N [mm]
  rect 1.55x0.7 smd: 1(-2.725,3.81) 2(-2.725,2.54) 3(-2.725,1.27) 4(-2.725,0) 5(-2.725,-1.27) 6(-2.725,-2.54) 7(-2.725,-3.81) 8(2.725,-3.81) 9(2.725,-2.54) 10(2.725,-1.27) 11(2.725,0) 12(2.725,1.27) 13(2.725,2.54) 14(2.725,3.81)
  silkscreen extent -3.5,-4.33 1.6,4.51, body extent -3,-4.31 3,4.34, height 1.56
SOP24N [mm] "SOP, 24-Leads, Body 15,90x5,65mm, Pitch 1,27mm, IPC Medium Density"
  oval 2.3x0.65 smd: 1(-4.525,6.985) 2(-4.525,5.715) 3(-4.525,4.445) 4(-4.525,3.175) 5(-4.525,1.905) 6(-4.525,0.635) 7(-4.525,-0.635) 8(-4.525,-1.905) 9(-4.525,-3.175) 10(-4.525,-4.445) 11(-4.525,-5.715) 12(-4.525,-6.985) 13(4.525,-6.985) 14(4.525,-5.715) 15(4.525,-4.445) 16(4.525,-3.175) 17(4.525,-1.905) 18(4.525,-0.635) 19(4.525,0.635) 20(4.525,1.905) 21(4.525,3.175) 22(4.525,4.445) 23(4.525,5.715) 24(4.525,6.985)
  silkscreen extent -4.65,-8 2.98,8, body extent -3,-8 3,8, height 2.65
SOP28 [mm]
  rect 3x0.64 smd: 1(0,0)
  oval 3x0.64 smd: 2(0,-1.27) 3(0,-2.54) 4(0,-3.81) 5(0,-5.08) 6(0,-6.35) 7(0,-7.62) 8(0,-8.89) 9(0,-10.16) 10(0,-11.43) 11(0,-12.7) 12(0,-13.97) 13(0,-15.24) 14(0,-16.51) 15(9.49,-16.51) 16(9.49,-15.24) 17(9.49,-13.97) 18(9.49,-12.7) 19(9.49,-11.43) 20(9.49,-10.16) 21(9.49,-8.89) 22(9.49,-7.62) 23(9.49,-6.35) 24(9.49,-5.08) 25(9.49,-3.81) 26(9.49,-2.54) 27(9.49,-1.27) 28(9.49,0)
  silkscreen extent 1.78,-17.14 7.71,0.64
SOP40 [mm]
  rect 3x0.7 smd: 1(-1.905,-0.635)
  oval 3x0.7 smd: 2(-1.905,-1.905) 3(-1.905,-3.175) 4(-1.905,-4.445) 5(-1.905,-5.715) 6(-1.905,-6.985) 7(-1.905,-8.255) 8(-1.905,-9.525) 9(-1.905,-10.795) 10(-1.905,-12.065) 11(-1.905,-13.335) 12(-1.905,-14.605) 13(-1.905,-15.875) 14(-1.905,-17.145) 15(-1.905,-18.415) 16(-1.905,-19.685) 17(-1.905,-20.955) 18(-1.905,-22.225) 19(-1.905,-23.495) 20(-1.905,-24.765) 21(9.295,-24.765) 22(9.295,-23.495) 23(9.295,-22.225) 24(9.295,-20.955) 25(9.295,-19.685) 26(9.295,-18.415) 27(9.295,-17.145) 28(9.295,-15.875) 29(9.295,-14.605) 30(9.295,-13.335) 31(9.295,-12.065) 32(9.295,-10.795) 33(9.295,-9.525) 34(9.295,-8.255) 35(9.295,-6.985) 36(9.295,-5.715) 37(9.295,-4.445) 38(9.295,-3.175) 39(9.295,-1.905) 40(9.295,-0.635)
  silkscreen extent 0.18,-25.4 7.21,0
SS12D07VG4NSGAPA [mm]
  round 1.3 hole 0.8: 1(0,0) 2(2,0) 3(4,0)
  round 1.875 hole 1.25: MH1(-2.1,0) MH2(6.1,0)
  silkscreen extent -4,-2.15 6.3,2.15, body extent -2.62,-2.15 6.63,2.15, height 7.1
SW_6_4 [mil]
  round 60 hole 39.37: 1(-157.9,-0.94) 2(-155.69,100) 3(-0.38,-0.94) 4(1.83,100) 5(157.79,-0.94) 6(160,100)
  oval 55.37x122.36 hole 103 slot 39.37 at 0 deg: 7(-315,50) 8(320,50)
  silkscreen extent -355,-100 355,210
"TAIYO YUDEN NRS5030" [mm] "Inductor, 2-Leads,Taiyo Yuden, NRS5030T4R7MMGJV"
  rect 1.5x4 smd: 1(-1.8,0) 2(1.8,0)
  silkscreen extent -1.57,-2.5 1.59,2.47, body extent -2.5,-2.5 2.5,2.5, height 3
TP [mm] "Test point"
  round 1.5 smd: 1(0,0)
UJCHP3SMTTR [mm]
  rect 0.7x1.15 smd: A5(-0.5,2.955) B5(0.5,2.955)
  rect 0.8x1.15 smd: A9(1.52,2.955) B9(-1.52,2.955)
  rect 0.9x1.15 smd: A12(2.75,2.955) B12(-2.75,2.955)
  round 1.9 hole 1.5: MH1(-4.32,2.95) MH2(4.32,2.95)
  round 2.25 hole 1.5: MH3(-4.32,-0.85) MH4(4.32,-0.85)
  silkscreen extent -4.47,-3.45 4.47,4.3, body extent -4.96,-3.45 4.97,3.6, height 3.46

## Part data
BT1: library part KLKLS7-TS1202, "KLS7-TS1202"
C1 C2 C3 C11 C12 C13 C15 C16 C18 C19 C20 C21 C23 C24 C25 C29 C36 C37 C39 C40 C41 C42 C45 C49 C50 C51 C54 C57 C59 C60 C63 C65 C66 C73 C74 C75 C76 C80: library part CBR08C160JAGAC, "CAP CER 16PF 250V C0G/NP0 0805", Capacitance="16 pF", Device Package="0805 (2012 Metric)", Manufacturer=KEMET, Operating Temperature="-55°C ~ 125°C", Supplier Part Number 1=399-8775-1-ND, Temperature Coefficient="C0G, NP0", Tolerance=±5%, Voltage - Rated=250V
C4 C5 C6 C7 C8 C9 C14 C17 C26 C38 C43 C52 C53 C56 C62: library part ECE-A1AKA470, "CAP ALUM 47UF 20% 10V RADIAL", Capacitance=47µF, Device Package="Radial, Can", Lifetime @ Temp.="1000 Hrs @ 85°C", Manufacturer="Panasonic Electronic Components", Operating Temperature="-40°C ~ 85°C", Ripple Current @ High Frequency="110.5mA @ 10kHz", Supplier Part Number 1=P806-ND, Tolerance=±20%, Voltage - Rated=10V
C22 C28 C31 C32 C33 C34 C35 C55 C58 C67 C68 C69 C70 C71 C72 C81: library part 80ZLH33MEFC6.3X11, "CAP ALUM 33UF 20% 80V RADIAL", Capacitance=33µF, Device Package="Radial, Can", Lifetime @ Temp.="6000 Hrs @ 105°C", Manufacturer=Rubycon, Operating Temperature="-40°C ~ 105°C", Ripple Current @ Low Frequency="112.14mA @ 120Hz", Supplier Part Number 1=1189-3051-ND, Tolerance=±20%, Voltage - Rated=80V
Con1: library part CARD_SLOT
CON2: library part DIN9
D1: library part 1N4148W-E3-08, "DIODE GEN PURP 75V 150MA SOD123", Current - Average Rectified (Io)=150mA, Current - Reverse Leakage @ Vr="100µA @ 100V", Manufacturer="Vishay Semiconductor Diodes Division", Operating Temperature - Junction="150°C (Max)", Package / Case=SOD-123, Supplier Part Number 1=1N4148W-E3-08CT-ND, Voltage - DC Reverse (Vr) (Max)=75V, Voltage - Forward (Vf) (Max) @ If="1.2V @ 100mA"
J1: library part 801-87-003-10-012101, "Connector", Manufacturer_Name=Preci-Dip, Mouser Part Number=437-8018700310012101
J2: library part "Header 3X2", "Header, 3-Pin, Dual row"
J3: library part UJC-HP-3-SMT-TR, "Connector", Manufacturer_Name="CUI Inc.", Mouser Part Number=490-UJC-HP-3-SMT-TR
J4 J6 J9: library part 161-0390-E, "Connector", Manufacturer_Name=Kobiconn
J5: "Connector", Manufacturer_Name="PRO SIGNAL", Manufacturer_Part_Number=PSG01601
J7 J8 Joy1 Joy2: "Receptacle Assembly, 9 Position, Right Angle", PackageDocument=O
JP1 JP2: library part JumperPad
L1: library part SRN8040-1R5Y, "FIXED IND 1.5UH 7A 11 MOHM SMD", Current - Saturation=8.2A, Current Rating (Amps)="7 A", DC Resistance (DCR)="11mOhm Max", Device Package=Nonstandard, Frequency - Self Resonant=55MHz, Inductance="1.5 µH", Inductance Frequency - Test="100 kHz", Manufacturer="Bourns Inc.", Operating Temperature="-40°C ~ 125°C", Q @ Freq="13 @ 7.96MHz", Supplier Part Number 1=SRN8040-1R5YCT-ND, Tolerance=±30%
L2: library part NRS5030T330MMGJV, "FIXED IND 33UH 800MA 292.5 MOHM", Current - Saturation=1.15A, Current Rating (Amps)="800 mA", DC Resistance (DCR)="292.5mOhm Max", Device Package=Nonstandard, Frequency - Self Resonant=10MHz, Inductance="33 µH", Inductance Frequency - Test="100 kHz", Manufacturer="Taiyo Yuden", Operating Temperature="-40°C ~ 125°C", Ratings=AEC-Q200, Supplier Part Number 1=587-6106-1-ND, Tolerance=±20%
R1 R2 R3 R4 R5 R6 R7 R8 R9 R10 R11 R12 R13 R15 R16 R17 R18 R19 R20 R21 R22 R23 R24 R25 R28 R29 R30 R31 R32 R33 R35 R36 R37 R39 R40 R43 R50 R51 R52 R56 R57 R58 R59 R60 R61 R62 R63 R64 R65 R66 R68 R70 R71 R72 R75 R76 R77 R78 R79 R80 R90 R91 R92 R95 R96 R97 R98: library part RCS0805604RFKEA, "RES SMD 604 OHM 1% 1/2W 0805", Device Package="0805 (2012 Metric)", Manufacturer="Vishay Dale", Operating Temperature="-55°C ~ 155°C", Power (Watts)="0.5W, 1/2W", Ratings=AEC-Q200, Resistance="604 Ohms", Supplier Device Package=0805, Supplier Part Number 1=541-RCS0805604RFKEACT-ND, Temperature Coefficient=±100ppm/°C, Tolerance=±1%
R53 R93 R99: library part ERJ-U6SFR10V, "RES 0.1 OHM 1% 1/4W 0805", Device Package="0805 (2012 Metric)", Manufacturer="Panasonic Electronic Components", Operating Temperature="-55°C ~ 155°C", Power (Watts)="0.25W, 1/4W", Ratings=AEC-Q200, Resistance="100 mOhms", Supplier Device Package=0805, Supplier Part Number 1=P.1BJCT-ND, Temperature Coefficient=±150ppm/°C, Tolerance=±1%
S1 S2: library part SS12D07VG4NSGAPA, "Switch", Manufacturer_Name="C & K COMPONENTS", Mouser Part Number=611-SS12D07VG4NSGAPA
S3: library part SK-13D08-G_5_E, "Switch", Arrow Part Number="SK-13D08-G 5 E", Manufacturer_Name="C & K COMPONENTS"
SW1: library part SWITCH_6_4
TP1 TP2 TP3 TP4 TP5 TP6 TP8 TP9 TP10 TP11 TP12 TP13 TP14 TP15: library part TP
U3: library part HM538123
U4 U6: "Operation amp", Arrow Part Number=OPA2134UA, Manufacturer_Name="Texas Instruments", Mouser Part Number=595-OPA2134UA
U5: library part CXA1645, "Video coder"
U10: library part 74HC257D,652, "Integrated Circuit", Manufacturer_Name=Nexperia, Mouser Part Number=771-HC257D652
U11: library part HEF4066BT,653, "Integrated Circuit", Manufacturer_Name=Nexperia, Mouser Part Number=771-HEF4066BTD-T
VC1 VC2: library part TZB4P400AB10R00, "Capacitor", Manufacturer_Name="Murata Electronics", Mouser Part Number=81-TZB4P400AB10R00
Y1 Y2: library part 12.000MHz_HC49_4H_30_50_-40+85_18pF_ATF, "Crystal or Oscillator", Manufacturer_Name=EUROQUARTZ, Manufacturer_Part_Number="12.000MHz HC49/4H/30/50/-40+85/18pF/ATF"

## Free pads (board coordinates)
  oval 157.48x98.43 hole 59.06 slot 118.11 at 0 deg: 14(1645.67,964.57) 14(1645.67,1220.47) 14(2232.28,964.57) 14(2232.28,1220.47)

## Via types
v1: diameter 25, hole 12, Top Layer to Bottom Layer, tented both sides, 269 vias
v2: diameter 19.68, hole 11.81, Top Layer to Bottom Layer, tented both sides, 183 vias
v3: diameter 31.5, hole 11.81, Top Layer to Bottom Layer, tented both sides, 82 vias
v4: diameter 23.62, hole 15.75, Top Layer to Bottom Layer, tented both sides, 36 vias
v5: diameter 35.43, hole 11.81, Top Layer to Bottom Layer, tented both sides, 35 vias
v6: diameter 39, hole 30, Top Layer to Bottom Layer, tented both sides, 7 vias
v7: diameter 19.68, hole 11.81, Top Layer to Bottom Layer, 2 vias

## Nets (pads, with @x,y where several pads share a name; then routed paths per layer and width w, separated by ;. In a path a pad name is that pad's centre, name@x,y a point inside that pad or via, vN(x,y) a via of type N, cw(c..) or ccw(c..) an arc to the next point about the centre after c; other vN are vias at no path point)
AVCC: C17.1 C18.1 C24.1 C58.1 C59.1 C62.1 C63.1 CON2.2 L2.2 R16.2 R21.1 R71.1 R72.1 R75.2 R76.2 R90.1 R91.1 R92.1 TP9.1 U4.8 U5.12 U5.19 U6.8 U7.160 U11.14 | length 18809.1
  Top Layer w10: 2520,3590 2693.23,3590 2766.62,3516.62 2720,3470 C24.1@2581.5,3470
  Top Layer w13: v2(3460,6880) 3530,6880 3710,7060 3710,7200 3640,7270 3640,7330 3660.32,7350.32 3720.32,7350.32 3752.05,7382.05 3752.05,7422.05 3779.3,7449.3 3835.51,7449.3 CON2.2@3882.56,7402.24
  Top Layer w25: C58.1@1840,6611.57 1836.87,6611.57 1824.78,6599.48 1824.78,6574.78 1710,6460 1550,6460 1230,6140 1230,3780 1420,3590 2520,3590 ; v2(2180,6350) 2130,6300 2130,6240 2148.9,6221.1 R16.2@2252.08,6221.1 ; v2(2610,6290) 2610,6380 2640,6410 U6.8@2703.54,6410 2760,6410 2769.86,6419.86 2809.86,6419.86 R21.1@2820,6430 ; U4.8@2701.81,5981.72 2719.03,5981.72 2787.32,6050 v2(2890,6050) ; v2(4130,6260) 4130,6120 4262.72,5987.28 U11.14@4340,5987.28 ; R75.2@4270,6215.94 v2(4270,6270) ; R76.2@4540,6215.94 v2(4540,6270) ; C63.1@4851.5,5580 4851.5,5747.84 4879.35,5775.69 4885.69,5775.69 4904.89,5794.89 5061.74,5794.89 U5.19@5061.85,5795 ; R72.1@5061.1,6910 5061.1,6848.9 5080,6830 5210,6830 5280,6900 v1(5340,6900) 5605.55,6900 R71.1@5615.55,6910 ; U5.12@5418.15,6095 5418.26,6095.11 5475.11,6095.11 5490,6110 5490,6258.5 5594.94,6363.44 5594.94,6365.41 5608.03,6378.5 C18.1@5610,6378.5 5613.62,6374.88 5776.38,6374.88 C17.1@5780,6371.26 ; v2(5790,6040) 5820,6070 6315.36,6070 6330,6055.36 R90.1@6330,6000 6496.46,6000 6511.1,5985.36 6511.1,5834.64 ; R92.1@6330,5640 6461.1,5640 6511.1,5690 6511.1,5834.64 ; R91.1@6330,5820 6496.46,5820 6511.1,5834.64
  Top Layer w39: C59.1@1597.01,6550 1590.92,6556.09 1590.92,6576.97 1586.98,6580.9 1586.98,6688.27 1750.51,6688.27 1827.2,6611.57 C58.1@1840,6611.57
  Bottom Layer w25: 4750,6268.86 4750,6520 4790,6560 5260,6560 5340,6640 v1(5340,6900) ; C62.1@4859.37,5750 4859.37,5978.98 5025.2,6144.8 ; 5780,6040 C17.1@5780,6371.26
  Bottom Layer w80: C58.1@1840,6611.57 1928.42,6611.57 ; v2(2890,6050) 2890,6243.14 2843.14,6290 v2(2610,6290) 2250,6290 1928.42,6611.57 ; v2(5790,6040) 5780,6040 5130,6040 5025.2,6144.8 4953.43,6216.57 4953.43,6222 4906.56,6268.86 4750,6268.86 4061.14,6268.86 3260,7070 2156.86,7070 2110,7023.14 2110,6830 1910,6630 1928.42,6611.57
  other v1: 4018.25,6314.09
GND: BT1.3 BT1.4 C1.2 C2.2 C3.2 C14.2 C15.2 C16.2 C17.2 C18.2 C21.2 C23.2 C24.2 C25.2 C26.2 C29.2 C36.2 C38.2 C39.1 C40.1 C41.1 C42.2 C43.2 C45.2 C49.1 C50.1 C51.2 C52.2 C53.2 C54.2 C55.2 C56.2 C57.2 C58.2 C59.2 C60.2 C62.2 C63.2 C65.2 C66.2 C74.2 C80.1 C81.2 Con1.32 Con1.33 Con1.47 Con1.64 CON2.10 J1.1 J2.1 J2.3 J2.5 J3.A12 J3.B12 J3.MH1 J3.MH2 J3.MH3 J3.MH4 J4.2 J4.3 J4.4 J5.4 J5.5 J5.9 J5.13 J5.17 J5.18 J5.21 J6.2 J6.3 J6.4 J7.8 J8.8 J9.2 J9.3 J9.4 Joy1.8 Joy1.10 Joy1.11 Joy2.8 Joy2.10 Joy2.11 JP2.3 L3.2 L4.2 pad.14 R1.2 R2.1 R6.2 R13.1 R17.2 R18.2 R19.2 R22.1 R29.2 R36.1 R39.2 R50.2 R53.2 R93.1 R95.1 R96.1 R97.2 R98.2 R99.2 S1.MH1 S1.MH2 S2.1 S2.MH1 S2.MH2 S3.3 S3.MH1 S3.MH2 SW1.7 SW1.8 U1.14 U2.14 U3.16 U3.29 U3.30 U3.40 U4.4 U5.1 U5.24 U6.4 U7.14 U7.29 U7.48 U7.49 U7.51 U7.77 U7.79 U7.101 U7.123 U7.146 U7.155 U9.7 U10.8 U10.15 U11.7 VC1.1 VC2.1 | length 6190.3
  Top Layer w10: C2.2@1768.5,4682.99 C2.2@1775.51,4690 ; v2(2760,3720) 2761.85,3718.15 2761.85,3702.4 U7.155@2869.58,3594.68 ; v2(2960,3070) 2960.18,3070 3014.21,3124.03 U7.14@3014.39,3124.03 ; U7.146@3032.5,3757.59 3032.5,3757.5 3112.92,3677.08 3112.92,3596.84 3117.71,3592.05 3117.71,3436.03 3236.19,3317.56 3242.44,3317.56 v2(3320,3240) ; C38.2@3330,2200.63 3331.65,2200.63 3360,2172.28 C54.2@3360,2070 ; v2(3560,4290) 3570,4280 ; 4030,3920 v2(4040,3930) ; U2.14@4440,3870 v2(4520,3870) ; C42.2@5029.02,3170.63 C42.2@5035.39,3177.01
  Top Layer w15: C66.2@2240,5450 R95.1@2240,5580 ; C63.2@4788.5,5580 4788.5,5719.54 4787.55,5720.49 4787.55,5741.8 C62.2@4788.5,5742.76 ; 4992.5,3834.9 4999.1,3828.3 4999.1,3810.9 v2(5000,3810) ; U5.24@5061.85,5545 5175,5545 5207.01,5512.99 C16.2@5207.01,5430 ; C18.2@5610,6441.5 5618.5,6450 C17.2@5780,6450
  Top Layer w20: R2.1@1620,5983.94 1620,5981.1 R2.1@1631.1,5970 ; C43.2@4865.39,3170.63 C42.2@5029.02,3170.63 ; R6.2@5631.1,6040 5631.1,5945.91 C74.2@5637.01,5940
  Top Layer w25: VC1.1@3110,1381.42 3141.87,1349.55 3210.45,1349.55 3240,1320 3292.99,1320 C60.2@3300,1312.99 C49.1@3300,1447.01
  Bottom Layer w10: 1205,2046.82 1205,2065 ; v2(3320,3240) 3986.87,3240 4154.14,3407.28 4154.14,3509.44 4159.69,3514.99 4159.69,3640.32 3984.84,3815.16 3984.84,4224.84 4300,4540 4470,4540 4562.69,4632.69 4566.28,4632.69 4583.59,4650 4620,4650 4670.12,4700.12 4687.7,4700.12 4747.58,4760 4891.21,4760 Con1.32@5048.42,4917.22 ; v2(3560,4290) 3560,4430 3810,4680
  other v1: 2468.31,646.75 4100.84,856.21 3030,950 3260,950 4430.84,956.21 4130.84,1006.21 3820.84,1026.21 2468.31,1032.86 3400,1140 2470.84,1236.21 3440,1370 3230,1380 1850,1470 2160,1470 2470,1470 1854.8,1720 2167.4,1720 2480,1720 3011.5,1731.75 3640,1770 3490,1780 4300,1830 3200,1880 4040,1920 4300,1920 4160,1940 1850,1970 2170,1970 4040,2010 4300,2010 2821.84,2056.08 4039.53,2060.94 2321.84,2076.08 2731.84,2106.08 4410,2250 1641.84,2256.08 2600,2300 3910,2390 4270,2480 1801.84,2556.08 2810,2560 3411.84,2596.08 1890,2740 4240,2760 1840,2780 3570,2930 1611.84,2936.08 3780,3080 3961.84,3136.08 5880,3160 2351.84,3226.08 2731.84,3246.08 1871.84,3256.08 3250,3390 1611.84,3396.08 5870,3420 5550,3430 2671.84,3516.08 1601.84,3526.08 5700,3600 6120,3600 4951.84,3736.08 5801.75,4238.76 5800,4430 5041.84,4666.08 5561.84,4696.08 5711.84,5236.08 4420,5340 4680,5340 4890,5340 5790,5340 6300,5350 6460,5350 6620,5350 5140,5360 2034.58,5368.24 1720,5370 1860,5370 5670,5380 3990,5400 4064.44,5400 3800,5410 4880.55,5420.55 5020,5450 6210,5450 6375,5450 6540,5450 4420,5460 2490,5480 2632,5480 2774,5480 2916,5480 3058,5480 3200,5480 4064.44,5509.13 3990,5510 1971.84,5536.08 5219.07,5549.81 1630,5570 6110,5590 6418.01,5591.56 3800,5600 1400,5610 4950,5610 5330,5610 4064.44,5618.26 3990,5620 2774,5630 2916,5630 3058,5630 3200,5630 6538.01,5631.56 2490,5657.5 2632,5657.5 5968.01,5671.56 6168.01,5681.56 4250,5690 4420,5690 4540,5690 4680,5690 6388.01,5691.56 6448.01,5701.56 6568.01,5721.56 1911.84,5726.08 4064.44,5727.38 3990,5730 4950,5740 6178.01,5771.56 6388.01,5771.56 6461.08,5778.3 3800,5790 4700,5790 4064.44,5836.51 3990,5840 6568.01,5846.56 6198.01,5861.56 4400,5870 6388.01,5871.56 6458.01,5871.56 1611.84,5876.08 1830,5880 4064.44,5945.64 3990,5950 6118.01,5951.56 6178.01,5951.56 6388.01,5951.56 6458.01,5951.56 1371.84,5956.08 1990,5970 4940,5970 6568.01,5971.56 3800,5980 4740,5980 3090,6020 1860,6050 4064.44,6054.77 3990,6060 1381.84,6086.08 2330,6090 1941.84,6146.08 2100,6170 3800,6170 3990,6170 5360,6170 5440,6170 6068.84,6170 6309.42,6170 6550,6170 2460,6190 5330,6290 1941.84,6316.08 6309.42,6335 6550,6340 3410,6360 3800,6360 1381.84,6396.08 5290,6410 4061.23,6486.98 1890,6490 3560,6500 6309.42,6500 6550,6500 1391.84,6566.08 4150,6590 4050,6620 2050,6630 2360,6670 2490,6670 2610,6670 2940.87,6676.4 2820,6680 1391.84,6686.08 5630,6720 5930,6720 1707.63,6767.48 2010,6850 2723.84,6876.16 2830.85,6876.16 2937.86,6876.16 6110,6910 6290,6910 3860,6920 2720,6980 2830,6980 2940,6980 3490,6980 3880,6980 4170,7010 4320,7010 1540,7030 4040,7110 4170,7114.14 4320,7115 1240,7120 3640,7200 990,7210 4170,7218.28 4320,7220 1430,7360 4140,7410 1430,7420 1430,7480 1430,7540 2210,7560 2840,7560 3490,7560
  other v2: 3810,2300 3880,2300 3790,2420 4160,4050
  other v3: 3300,590 3530,590 3760,590 1380,650 1670,650 1960,650 2250,650 4530,740 4864.02,740 1270,1150 930,1320 1270,1380 5220,1450 5860,1450 6610,1520 930,1582.66 1270,1610 6480,1790 5710,1820 6130,1830 1270,1840 930,1845.32 5420,2060 930,2107.99 6290,2111.97 5210,2300 930,2370.65 930,2633.31 6610,2723.33 3070,2800 930,2895.97 1350,2940 3580,3060 6620,3110 930,3158.64 1350,3160 6320,3170 4100,3290 6320,3326.67 1350,3370 3358.23,3396.58 2280,3420 930,3421.3 6320,3510 6610,3530 6320,3640 930,3683.96 6320,3796.67 1568.88,3810.81 1778.88,3810.81 1988.88,3810.81 2198.88,3810.81 2408.88,3810.81 2618.88,3810.81 6320,3920 6610,3933.33 930,3946.62 1680,3960 1890,3960 2100,3960 2310,3960 6320,4110 930,4209.29 1640,4210 1880,4210 6610,4336.67 6320,4360 930,4471.95 2190,4580 6310,4650 930,4734.61 6610,4740 930,4997.27 6610,5143.33 930,5259.94 930,5522.6 930,5785.26 930,6047.92 930,6310.59
  other v5: 5980,640 5200,738.03 5760,1010 3090,2050 5120,2050 3160,2160 3450,2330 4890,2450 6360,2490 3070,2540 2130,2630 3842.81,2685.91 2940,2720 4719.46,2787.12 5120,2830 3440,2950 4899.46,2967.12 1940,2970 4709.46,2977.12 2530,2980 5249.46,3057.12 5290,3320 4360,3440 4769.46,3517.12 4630,3600 5200,3750 4670,3880 5460,4570 5660,5000 6010,5010 4060,5020 4150,5030 4540,5030
NetBT1_1: BT1.1 BT1.2 C41.2 R56.2 U7.80 | length 3603.3
  Top Layer w10: U7.80@4335.83,3359.35 4431.08,3264.11 4698.7,3264.11 4832.77,3130.04 5100.39,3130.04 5141.46,3171.1 R56.2@5145.39,3171.1 ; v2(4790,1650) 4790,2711.82 5050.68,2972.5 5083.45,2972.5 5128.39,3017.44 C41.2@5128.39,3060 C41.2@5145.39,3077.01 ; BT1.1@4947.87,1215 BT1.1@4948.94,1216.06 ; v2@4948.94,1468.94 v2(4950,1470)
  Top Layer w20: BT1.1@4948.94,1216.06 v2@4948.94,1468.94 ; C41.2@5145.39,3077.01 R56.2@5145.39,3171.1
  Top Layer w25: BT1.1@4947.87,1215 BT1.2@5440,1215
  Bottom Layer w10: v2(4790,1650) 4948.15,1491.85 4948.15,1471.85 v2(4950,1470)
